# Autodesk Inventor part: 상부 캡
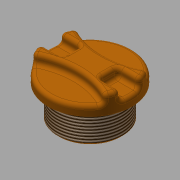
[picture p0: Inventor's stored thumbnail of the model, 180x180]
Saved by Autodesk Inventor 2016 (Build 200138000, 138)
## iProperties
Created: 2016-09
Part Number: 상부 캡
Material: ABS 플라스틱
Document SubType Name: Modeling
Designer: mduedu
Density: 1.06 g/cm^3
Mass: 23.0415 g
Surface Area: 69.3209 cm^2
Volume: 21.7373 cm^3
Appearance: 주황색
Author: mduedu
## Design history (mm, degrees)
sketch "스케치1"
  geometry: C1 r 22.5 at (0, 0); 1 further point
  constraints: 1 centre point, 1 coincident
  dimensions: "d0" = 45 diameter of C1
extrude "돌출1" new body sketch "스케치1" distance "d1" = 10; taper "d2" = 0 deg
sketch "스케치2" dims "d4" = 80
  geometry: C1 r 22.5 at (0, 0) reference; 3 further points
  constraints: 3 vertical alignment, 2 other
  dimensions: "d3" = 7 distance of point (0, 7) point (0, 0)
extrude "돌출2" cut sketch "스케치2" distance "d5" = 5; taper "d6" = 0 deg
sketch "스케치3"
  geometry: L1 (-22.5, 0)-(0, 0); L2 (-21.937, 5)-(-10, 5); L3 (-10, 5)-(-10, -5); L4 (-10, -5)-(-21.937, -5); A1 r 22.5 centre (0, 0) between (-19.118, 11.864) and (-19.118, -11.864) reference; A2 r 22.5 centre (0, 0) between (-21.937, 5) and (-21.937, -5); 1 further point
  constraints: 8 end point, 5 point on circle, 2 horizontal, 1 centre point, 1 coincident, 1 parallel, 1 perpendicular, 1 symmetric about line
  dimensions: "d7" = 10 distance from line of L3 point (0, 0); "d8" = 10 distance of L2.end L3.end
extrude "돌출3" cut sketch "스케치3" distance "d9" = 5; taper "d10" = 0 deg
fillet "모깎기1" dims "d11" = 2
fillet "모깎기2" dims "d12" = 2
fillet "모깎기3" dims "d13" = 2
sketch "스케치4"
  geometry: C1 r 17.5 at (0, 0); 1 further point
  constraints: 1 centre point, 1 coincident
  dimensions: "d14" = 35 diameter of C1
extrude "돌출4" join sketch "스케치4" distance "d15" = 17; taper "d16" = 0 deg
sketch "스케치5"
  geometry: C1 r 12.5 at (0, 0); 1 further point
  constraints: 1 centre point, 1 coincident
  dimensions: "d17" = 25 diameter of C1
extrude "돌출5" cut sketch "스케치5" distance "d18" = 10; taper "d19" = 0 deg
fillet "모깎기4" dims "d20" = 3
sketch "스케치6"
  geometry: L1 (0, 22.5)-(0, -22.5) reference; L2 (0, 17.5)-(-1, 17.5); L3 (-1, 17.5)-(-1, 16.5); L4 (-1, 16.5)-(0, 16.5); L5 (0, 16.5)-(0, 17.5); L6 (0, 17.5)-(-17, 17.5) reference; L7 (-22.401, 0)-(15.404, 0) reference; 1 further point
  constraints: 8 end point, 2 parallel, 1 collinear, 1 horizontal, 1 perpendicular, 1 point on line
  dimensions: "d26" = 1 distance of L2.start L2.end; "d28" = 1 distance of L2.end L3.end
revolve "회전1" sketch "스케치6" stored, may be unused: angle "d29" = 90 deg
feature "스레드1" dims "d21" = 10, "d22" = 0
chamfer "모따기1" distance "d23" = 1; stored, may be unused: second distance "d24" = 2, angle "d25" = 45 deg
chamfer "모따기2" distance "d30" = 1; stored, may be unused: second distance "d31" = 2, angle "d32" = 45 deg
node "솔리드1"
mirror "대칭1"
mirror "대칭2"
node "투영된 루프1"
